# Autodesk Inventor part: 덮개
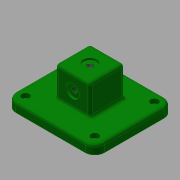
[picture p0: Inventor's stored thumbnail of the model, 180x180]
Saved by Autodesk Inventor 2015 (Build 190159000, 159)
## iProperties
Created: 2017-08
Part Number: 덮개
Material: 알루미늄 6061
Document SubType Name: Modeling
Designer: mduedu
Density: 1 g/cm^3
Appearance: 진녹색
Author: mduedu
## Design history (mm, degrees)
sketch "스케치1"
  geometry: L1 (46, -41)-(-46, -41); L2 (-46, -41)-(-46, 41); L3 (-46, 41)-(46, 41); L4 (46, 41)-(46, -41); 1 further point
  constraints: 8 end point, 2 parallel, 1 horizontal, 1 perpendicular
  dimensions: "d0" = 92 distance of L2.end L3.end; "d2" = 82 distance of L1.end L2.end; "d3" = 41 distance from line of L3 point (0, 0) (= 0.5 x d2); "d4" = 46 distance from line of point (0, 0) L4 (= 0.5 x d0)
extrude "돌출1" new body sketch "스케치1" distance "d5" = 10; taper "d6" = 0 deg
sketch "스케치2"
  geometry: L1 (-18, -18)-(18, -18); L2 (18, -18)-(18, 18); L3 (18, 18)-(-18, 18); L4 (-18, 18)-(-18, -18); L5 (-18, -18)-(18, 18); L6 (18, -18)-(-18, 18); 1 further point
  constraints: 12 end point, 2 midpoint, 2 parallel, 2 perpendicular, 1 horizontal
  dimensions: "d7" = 36 distance of L2.end L3.end
extrude "돌출2" join sketch "스케치2" distance "d9" = 32; taper "d10" = 0 deg
sketch "스케치3"
  geometry: L1 (-26, -26)-(26, -26); L2 (26, -26)-(26, 26); L3 (26, 26)-(-26, 26); L4 (-26, 26)-(-26, -26); L5 (-26, -26)-(26, 26); L6 (26, -26)-(-26, 26); 1 further point
  constraints: 12 end point, 2 midpoint, 2 parallel, 2 perpendicular, 1 horizontal
  dimensions: "d11" = 52 distance of L3.end L2.end
extrude "돌출3" join sketch "스케치3" distance "d12" = 6; taper "d13" = 0 deg
sketch "스케치4"
  geometry: L1 (-17, -17)-(17, -17); L2 (17, -17)-(17, 17); L3 (17, 17)-(-17, 17); L4 (-17, 17)-(-17, -17); L5 (-17, -17)-(17, 17); L6 (17, -17)-(-17, 17); 1 further point
  constraints: 12 end point, 2 midpoint, 2 parallel, 2 perpendicular, 1 horizontal
  dimensions: "d14" = 34 distance of L2.end L3.end
extrude "돌출4" cut sketch "스케치4" distance "d16" = 5; taper "d17" = 0 deg
sketch "스케치5"
  geometry: C1 r 9 at (0, 0); 1 further point
  constraints: 1 centre point, 1 coincident
  dimensions: "d18" = 18 diameter of C1
extrude "돌출5" cut sketch "스케치5" distance "d19" = 34; taper "d20" = 0 deg
sketch "스케치6"
  geometry: 2 further points
  constraints: 1 coincident
hole "구멍1" sketch "스케치6" at (0, 0) diameter "d21" = 5.917; stored, may be unused: countersink angle "d25" = 90 deg, drill point angle "d27" = 118 deg; dims "d22" = 6, "d23" = 14, "d24" = 2, "d26" = 8
sketch "스케치7"
  geometry: L1 (-28, -10)-(64, -10) reference; 3 further points
  constraints: 1 midpoint, 1 vertical alignment
  dimensions: "d47" = 26 distance from line of point (18, 16) L1
hole "구멍2" sketch "스케치7" at (18, 16) diameter "d29" = 5.917; stored, may be unused: countersink angle "d33" = 90 deg, drill point angle "d35" = 118 deg; dims "d30" = 6, "d31" = 14, "d32" = 2, "d34" = 8
fillet "모깎기1" dims "d36" = 10
fillet "모깎기2" dims "d37" = 3
fillet "모깎기3" dims "d38" = 3
fillet "모깎기4" dims "d39" = 3
fillet "모깎기5" dims "d40" = 3
chamfer "모따기1" distance "d41" = 1; stored, may be unused: second distance "d42" = 2, angle "d43" = 45 deg
fillet "모깎기6" dims "d44" = 3
fillet "모깎기7" dims "d45" = 3
fillet "모깎기8" dims "d46" = 3
sketch "스케치8"
  geometry: A1 r 10 centre (-36, -31) between (-46, -31) and (-36, -41) reference; A2 r 10 centre (-36, 31) between (-36, 41) and (-46, 31) reference; A3 r 10 centre (36, 31) between (46, 31) and (36, 41) reference; A4 r 10 centre (36, -31) between (36, -41) and (46, -31) reference; 5 further points
  constraints: 4 coincident
sketch "스케치9"
  geometry: 4 further points
  constraints: 4 other
hole "구멍3" sketch "스케치9" at (-36, -31), (-36, 31), (36, 31), (36, -31) diameter "d48" = 4.5; stored, may be unused: countersink angle "d52" = 90 deg, drill point angle "d54" = 0 deg; dims "d49" = 6, "d50" = 8, "d51" = 4.6, "d53" = 8
node "솔리드1"
